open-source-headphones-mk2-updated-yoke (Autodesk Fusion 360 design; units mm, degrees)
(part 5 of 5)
sketch "Sketch21" plane through (0, 0, 36) normal (0, 0, 1) x axis (-1, 0, 0)
  line L1 (-70.6699, 179.8205) -> (-76.1699, 170.2942)
  line L2 (-80.6292, 185.5705) -> (-70.6699, 179.8205)
  line L3 (-90.4356, 168.5852) -> (-80.6292, 185.5705)
  line L4 (-86.2462, 149.3972) -> (-90.4356, 168.5852)
  curve K1 (-86.2462, 149.3972) -> (0, 72.5)
  curve K2 (86.2462, 149.3972) -> (0, 72.5)
  line L5 (90.4356, 168.5852) -> (86.2462, 149.3972)
  line L6 (80.6292, 185.5705) -> (90.4356, 168.5852)
  line L7 (70.6699, 179.8205) -> (80.6292, 185.5705)
  line L8 (74.1699, 173.7583) -> (70.6699, 179.8205)
  line L9 (81.2713, 177.8583) -> (74.1699, 173.7583)
  line L10 (86.3713, 169.0249) -> (81.2713, 177.8583)
  line L11 (85.989, 166.4546) -> (86.3713, 169.0249)
  curve K3 (0, 74) -> (85.989, 166.4546)
  curve K4 (0, 74) -> (-85.989, 166.4546)
  line L12 (-86.3713, 169.0249) -> (-85.989, 166.4546)
  line L13 (-83.2713, 174.3942) -> (-86.3713, 169.0249)
  line L14 (-76.1699, 170.2942) -> (-83.2713, 174.3942)
  line L15 (-75.4199, 171.5933) -> (-76.1699, 170.2942)
  line L16 (-78.0179, 173.0933) -> (-75.4199, 171.5933)
  line L17 (-78.0179, 173.0933) -> (-78.7679, 171.7942)
  line L18 (-76.9279, 172.4639) -> (-78.7679, 171.7942)
  line L19 (-76.8098, 171.7942) -> (-78.7679, 171.7942)
  line L20 (-76.6681, 172.3139) -> (-76.9279, 172.4639)
  line L21 (-76.3281, 170.3856) -> (-76.6681, 172.3139)
  line L22 (-74.71, 172.3139) -> (-76.6681, 172.3139)
  line L23 (0, 74) -> (0, 72.5)
  line L24 (78.0179, 173.0933) -> (78.7679, 171.7942)
  line L25 (76.6681, 172.3139) -> (76.9279, 172.4639)
  line L26 (74.71, 172.3139) -> (76.6681, 172.3139)
  line L27 (78.0179, 173.0933) -> (75.4199, 171.5933)
  line L28 (76.9279, 172.4639) -> (78.7679, 171.7942)
  line L29 (76.3281, 170.3856) -> (76.6681, 172.3139)
  line L30 (75.4199, 171.5933) -> (76.1699, 170.2942)
  line L31 (76.8098, 171.7942) -> (78.7679, 171.7942)
  line L32 (76.1699, 170.2942) -> (78.7679, 171.7942)
  point P2 (-76.1699, 170.2942)
  point P20 (-76.1699, 170.2942)
  point P25 (-76.9279, 172.4639)
  point P28 (-76.3281, 170.3856)
  point P7 (0, 72.5)
  point P30 (0, 72.5)
  point P16 (0, 74)
  point P31 (0, 74)
  point P40 (76.1699, 170.2942)
  point P34 (76.1699, 170.2942)
  point P21 (-75.4199, 171.5933)
  point P36 (75.4199, 171.5933)
  point P22 (-78.0179, 173.0933)
  point P42 (78.0179, 173.0933)
  point P23 (-78.7679, 171.7942)
  point P35 (78.7679, 171.7942)
  point P24 (-78.0179, 173.0933)
  point P38 (78.0179, 173.0933)
  point P33 (76.9279, 172.4639)
  point P26 (-76.8098, 171.7942)
  point P32 (76.8098, 171.7942)
  point P27 (-76.6681, 172.3139)
  point P39 (76.6681, 172.3139)
  point P41 (76.3281, 170.3856)
  point P29 (-74.71, 172.3139)
  point P37 (74.71, 172.3139)
  point P43 (76.1699, 170.2942)
  coincident P2 P20
  perpendicular L14 L15
  perpendicular L1 L16
  horizontal L19
  coincident L16 P25
  parallel L16 L20
  horizontal L22
  coincident L14 P28
  coincident P7 P30
  coincident P16 P31
  symmetric P2 L23 P40
  symmetric P20 L23 P34
  symmetric P21 L23 P36
  symmetric P22 L23 P42
  symmetric P23 L23 P35
  symmetric P24 L23 P38
  symmetric P25 L23 P33
  symmetric P26 L23 P32
  symmetric P27 L23 P39
  symmetric P28 L23 P41
  symmetric P29 L23 P37
  coincident P40 P43
  perpendicular L30 L32
  dimension "d657" distance P20 P21 = 1.5
  dimension "d658" distance P21 P22 = 3
  dimension "d659" = -3
  dimension "d660" angle L18 L19 = 20
  dimension "d661" distance P25 P27 = 0.3
  dimension "d662" angle L21 L22 = 80
sketch "Sketch22" plane through (-130.0009, -75.0561, 0) normal (0.866, 0.5, 0) x axis (-0.5, 0.866, 0)
  line L1 (-113.3942, 1) -> (-120.3942, 1)
  line L2 (-113.3942, 35) -> (-113.3942, 1)
  line L3 (-120.3942, 35) -> (-113.3942, 35)
  line L4 (-120.3942, 1) -> (-120.3942, 35)
  line L5 (-109.3942, 1) -> (-120.3942, 1)
  line L6 (-109.3942, 8.4) -> (-109.3942, 1)
  line L7 (-120.3942, 8.4) -> (-109.3942, 8.4)
  line L8 (-120.3942, 1) -> (-120.3942, 8.4)
  line L9 (-109.3942, 1) -> (-120.3942, 1)
  line L10 (-109.3942, 0) -> (-109.3942, 1)
  line L11 (-120.3942, 0) -> (-109.3942, 0)
  line L12 (-120.3942, 1) -> (-120.3942, 0)
  line L13 (-113.3942, 0) -> (-113.3942, 1)
  line L14 (-113.3942, 12.4) -> (-109.3942, 8.4)
  line L15 (-115.051, 8.4) -> (-109.3942, 8.4)
  point P2 (-120.3942, 1)
  point P6 (-120.3942, 1)
  point P10 (-120.3942, 1)
  point P3 (-113.3942, 1)
  point P14 (-113.3942, 1)
  point P15 (-113.3942, 0)
  point P16 (-113.3942, 12.4)
  point P7 (-109.3942, 1)
  point P9 (-120.3942, 8.4)
  point P13 (-120.3942, 0)
  horizontal L5
  vertical L6
  horizontal L7
  vertical L8
  coincident P2 P6
  horizontal L9
  vertical L10
  horizontal L11
  vertical L12
  coincident P2 P10
  coincident P3 P14
  coincident L11 P15
  perpendicular L11 L13
  horizontal L15
  coincident L2 P16
  dimension "d663" distance P6 P7 = 11
  dimension "d664" distance P6 P9 = 7.4
  dimension "d665" distance P10 P13 = 1
  dimension "d666" angle L14 L15 = 45
extrude "Extrude39" add sketch "Sketch22" profile of L2 L5 L6 L7 L9 L10 L11 L13 L14 against normal blind 9.2
extrude "Extrude40" cut of existing geometry blind -4
extrude "Extrude41" cut sketch "Sketch21" profile of L14 L16 L18 L20 L21 L25 L27 L28 L29 L32 against normal blind 36
sketch "40mm adapter for 52mm" plane through (0, 0, 0) normal (0, 0, 1) x axis (1, 0, 0)
  circle C1 centre (180, 25) radius 24.9
  circle C2 centre (180, 25) radius 20.15
  circle C3 centre (180, 25) radius 18.5
  circle C4 centre (180, 25) radius 21.5
  concentric C1 C2
  concentric C2 C3
  concentric C1 C4
  dimension "d673" diameter C1 = 49.8
  dimension "d674" diameter C2 = 40.3
  dimension "d675" diameter C3 = 37
  dimension "d676" diameter C4 = 43
extrude "Extrude7" new body sketch "40mm adapter for 52mm" profile of C2 C3 along normal blind 1.5
extrude "Extrude8" add sketch "40mm adapter for 52mm" profile of C2 C4 along normal blind 3
extrude "Extrude9" add sketch "40mm adapter for 52mm" profile of C1 C4 along normal blind 2
component_from_bodies "Body->Comp3"
sketch "Sketch1" plane through (0, 0, 0) normal (0, 0, 1) x axis (1, 0, 0)
  line L1 (219.4437, 9.4437) -> (235, 25)
  line L2 (213, 25) -> (235, 25)
  line L3 (250.5563, 9.4437) -> (235, 25)
  line L4 (257, 25) -> (235, 25)
  circle C1 centre (235, 25) radius 22
  circle C2 centre (235, 25) radius 20.1
  circle C3 centre (235, 25) radius 18
  point P2 (235, 25)
  point P4 (235, 25)
  point P5 (219.4437, 9.4437)
  point P3 (235, 25)
  point P7 (235, 25)
  point P8 (250.5563, 9.4437)
  concentric C1 C2
  horizontal L2
  coincident P2 P4
  coincident C1 P5
  horizontal L4
  coincident P3 P7
  coincident C1 P8
  concentric C2 C3
  dimension "d683" diameter C1 = 44
  dimension "d684" diameter C2 = 40.2
  dimension "d685" angle L1 L2 = 45
  dimension "d686" angle L3 L4 = 45
  dimension "d687" diameter C3 = 36
extrude "Extrude1" new body sketch "Sketch1" profile of C1 C2 L1 L3 along normal blind 6 bodies "40mm Top adapter"
extrude "Extrude2" add sketch "Sketch1" profile of C2 L1 L3 C3 along normal blind 4
copy_paste_bodies "CopyPasteBodies1"
move "Move1"
offset_faces "OffsetFaces1" distance 2
offset_faces "OffsetFaces2" distance -2
copy_paste_bodies "CopyPasteBodies3"
move "Move3"
offset_faces "OffsetFaces3" distance 0.5
offset_faces "OffsetFaces4" distance -0.5
position "Position1"
copy_paste_bodies "CopyPasteBodies4"
move "Move3"
component_from_bodies "Body->Comp4"
copy_paste_bodies "CutPasteBodies1"
extrude "Extrude1" cut of existing geometry blind -1.5
move_face "MoveFace1"
move_face "MoveFace2"
move "Move4"
move "Move5"
move "Move6"
move "Move7"
move "Move8"
move "Move4"
move "Move1"
move "Move5"
move "Move2"
move "Move6"
move "Move7"
move_face "MoveFace2"
move_face "MoveFace3"
chamfer "Chamfer11" distance 60 distance 1.1
copy_paste_bodies "CopyPasteBodies1"
move "Move1"
sketch "Sketch23" plane through (0, -95, 0) normal (0, -1, 0) x axis (1, 0, 0)
  line L1 (5.5, 20) -> (-5.5, 20)
  line L2 (5.5, 31.1) -> (5.5, 20)
  line L3 (-5.5, 31.1) -> (5.5, 31.1)
  line L4 (-5.5, 20) -> (-5.5, 31.1)
  line L5 (-1.613, 21.999) -> (0, 22.5861)
  line L6 (-2.913, 27.0603) -> (-3.9391, 24.2412)
  line L7 (3.9391, 24.2412) -> (2.913, 27.0603)
  line L8 (0, 22.5861) -> (1.613, 21.999)
  line L9 (3.1, 26) -> (-3.1, 26)
  line L10 (3.1, 22.9) -> (3.1, 26)
  line L11 (-3.1, 22.9) -> (3.1, 22.9)
  line L12 (-3.1, 26) -> (-3.1, 22.9)
  arc A1 centre (0, 26) radius 4.3139 clockwise from (-1.613, 21.999) to (-3.9391, 24.2412)
  arc A2 centre (0, 26) radius 3.1 clockwise from (-2.913, 27.0603) to (2.913, 27.0603)
  arc A3 centre (0, 26) radius 4.3139 clockwise from (3.9391, 24.2412) to (1.613, 21.999)
  circle C1 centre (0, 26) radius 3.1
  point P15 (-3.1, 26)
  point P16 (3.1, 26)
  point P18 (-3.1, 22.9)
  concentric A1 C1
  horizontal L9
  vertical L10
  horizontal L11
  vertical L12
  coincident C1 P15
  dimension "d724" diameter C1 = 6.2
  dimension "d725" distance P15 P16 = 6.2
  dimension "d726" distance P15 P18 = 3.1
extrude "Extrude42" add sketch "Sketch23" profile of L5 A1 L6 L7 A3 L8 C1 L10 L11 L12 against normal blind 5
extrude "Extrude43" cut sketch "Sketch23" profile of A1 A3 L10 L11 L12 against normal blind 5
copy_paste_bodies "CopyPasteBodies2"
move "Move2"
sketch "Sketch24" plane through (0, -95, 0) normal (0, -1, 0) x axis (1, 0, 0)
  line L1 (-3.1, 46) -> (-3.1, 42.9)
  line L2 (3.1, 42.9) -> (3.1, 46)
  line L3 (-3.1, 42.9) -> (3.1, 42.9)
  line L4 (5.5, 40) -> (-5.5, 40)
  line L5 (5.5, 51.1) -> (5.5, 40)
  line L6 (-5.5, 51.1) -> (5.5, 51.1)
  line L7 (-5.5, 40) -> (-5.5, 51.1)
  line L8 (-3.1, 42.9) -> (3.1, 42.9)
  line L9 (-3.1, 49.1) -> (-3.1, 42.9)
  line L10 (3.1, 49.1) -> (-3.1, 49.1)
  line L11 (3.1, 42.9) -> (3.1, 49.1)
  line L12 (-3.1, 49.1) -> (3.1, 42.9)
  line L13 (3.1, 49.1) -> (-3.1, 42.9)
  arc A1 centre (0, 46) radius 3.1 clockwise from (-3.1, 46) to (3.1, 46)
  circle C1 centre (0, 46) radius 4.3841
  point P15 (0, 46)
  point P6 (3.1, 42.9)
  point P11 (3.1, 42.9)
  point P5 (0, 46)
  point P16 (0, 46)
  horizontal L8
  perpendicular L8 L9
  parallel L8 L10
  parallel L9 L11
  coincident L12 P15
  coincident L13 P15
  coincident P6 P11
  coincident P5 P15
  coincident P15 P16
  coincident P11 C1
extrude "Extrude44" cut sketch "Sketch24" profile of L1 A1 L2 L3 L8 L9 L10 L11 C1 against normal blind 5
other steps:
base_feature "Base Feature1" bodies "40mm Bottom adapter"
base_feature "Base Feature1" bodies "50mm Pad Mount", "50mm Pad Mount NG"
base_feature "Base Feature2" bodies "40mm Pad Mount", "45mm Pad Mount", "52mm Pad Mount", "44mm Pad Mount", "40mm Pad Mount NG", "45mm Pad Mount NG", "52mm Pad Mount NG", "44mm Pad Mount NG"
base_feature "Base Feature2" bodies "40mm Bottom adapter", "40mm Top adapter", "44mm Bottom adapter", "44mm Top adapter"
base_feature "Base Feature4" bodies "44mm Bottom adapter", "44mm Top adapter", "45mm Bottom adapter", "45mm Top adapter"
base_feature "Base Feature1" bodies "50mm Pad Mount"
base_feature "Base Feature1" bodies "Pad Mount"
base_feature "Base Feature2" bodies "Driver Clamp"
base_feature "Base Feature4" bodies "50mm Pad Mount", "40mm Pad Mount", "52mm Pad Mount", "44mm Pad Mount", "45mm Pad Mount"
base_feature "Base Feature1" bodies "Yoke", "Yoke No Rotation"
base_feature "Base Feature2" bodies "Yoke (1)", "Yoke +-90 Degree Rotation"
base_feature "Base Feature2" bodies "Driver Clamp", "Driver Clamp (1)"
base_feature "Base Feature3" bodies "Closed Shell", "Closed Shell (1)"
base_feature "Base Feature4" bodies "Open Shell", "Custom Shell Body"
base_feature "Base Feature1" bodies "Pad Mount", "40mm Pad Mount"
base_feature "Base Feature2" bodies "Driver Clamp", "40mm Middle Body"
base_feature "Base Feature3" bodies "Driver Clamp (1)", "Pad Mount (1)", "52mm Middle Body", "52mm Pad Mount"
base_feature "Base Feature4" bodies "Pad Mount (2)", "Driver Clamp (2)", "44mm Pad Mount", "44mm Middle Body"
base_feature "Base Feature5" bodies "44mm Pad Mount", "44mm Driver Clamp", "45mm Pad Mount", "45mm Middle Body"
base_feature "Base Feature5" bodies "Custom Shell Grill", "Custom Shell Closed Grill"
create_component "CreateComponent1"
remove_body "RemoveBody1"
create_component "CreateComponent2"
create_component "CreateComponent3"
remove_body "RemoveBody2"
remove_body "RemoveBody3"
create_component "CreateComponent4"
remove_body "RemoveBody4"
create_component "CreateComponent5"
remove_body "RemoveBody5"
remove_body "RemoveBody6"
remove_body "RemoveBody7"
remove_body "RemoveBody8"
remove_body "RemoveBody9"
named bodies: "50mm Pad Mount", "50mm Middle Body", "Closed Shell", "Driver Clamp", "Driver Clamp (1)", "Closed Shell (1) (1)", "Closed Shell (1) (2)", "Closed Shell (1) (3)", "Open Shell", "Headband Arc", "Yoke +-20 Degree Rotation", "Screw Holder", "Headband Clip", "Pad Mount", "40mm Pad Mount", "40mm Middle Body", "Pad Mount (1)", "52mm Middle Body", "52mm Pad Mount", "Pad Mount (2)", "Driver Clamp (2)", "44mm Pad Mount", "44mm Middle Body", "44mm Driver Clamp", "45mm Pad Mount", "45mm Middle Body", "TPU Suspension Pad", "45cm 1.75mm Unprinted TPU", "Closed Shell (1)", "40mm Bottom adapter", "40mm Top adapter", "44mm Bottom adapter", "44mm Top adapter", "45mm Bottom adapter", "45mm Top adapter", "50mm Pad Mount NG", "40mm Pad Mount NG", "45mm Pad Mount NG", "52mm Pad Mount NG", "44mm Pad Mount NG", "Custom Shell Body", "Custom Shell Open Grill", "Custom Shell Grill", "Custom Shell Closed Grill", "Yoke", "Yoke No Rotation", "Yoke (1)", "Yoke +-90 Degree Rotation"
